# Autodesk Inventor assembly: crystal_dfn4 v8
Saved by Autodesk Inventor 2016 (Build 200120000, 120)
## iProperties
Created: 2016-09
Part Number: crystal_dfn4 v8
Document SubType Name: Assembly
Designer: Administrator
Author: Administrator
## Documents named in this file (5)
- c:\worker\convert-fusion-aug-2016\tmp\job-1\13\output\files\2055b865-881d-4af8-ae30-e7b46ec3c804\crystal_dfn4 v8.iam
- c:\worker\convert-fusion-aug-2016\tmp\job-1\13\output\files\2055b865-881d-4af8-ae30-e7b46ec3c804\Component38.ipt
- c:\worker\convert-fusion-aug-2016\tmp\job-1\13\output\files\2055b865-881d-4af8-ae30-e7b46ec3c804\Component39.ipt
- c:\worker\convert-fusion-aug-2016\tmp\job-1\13\output\files\2055b865-881d-4af8-ae30-e7b46ec3c804\Component40.ipt
- c:\worker\convert-fusion-aug-2016\tmp\job-1\13\output\files\2055b865-881d-4af8-ae30-e7b46ec3c804\Component41.ipt
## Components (4 placed, 4 different names)
1. Component38:1
2. Component39:1
3. Component40:1
4. Component41:1
